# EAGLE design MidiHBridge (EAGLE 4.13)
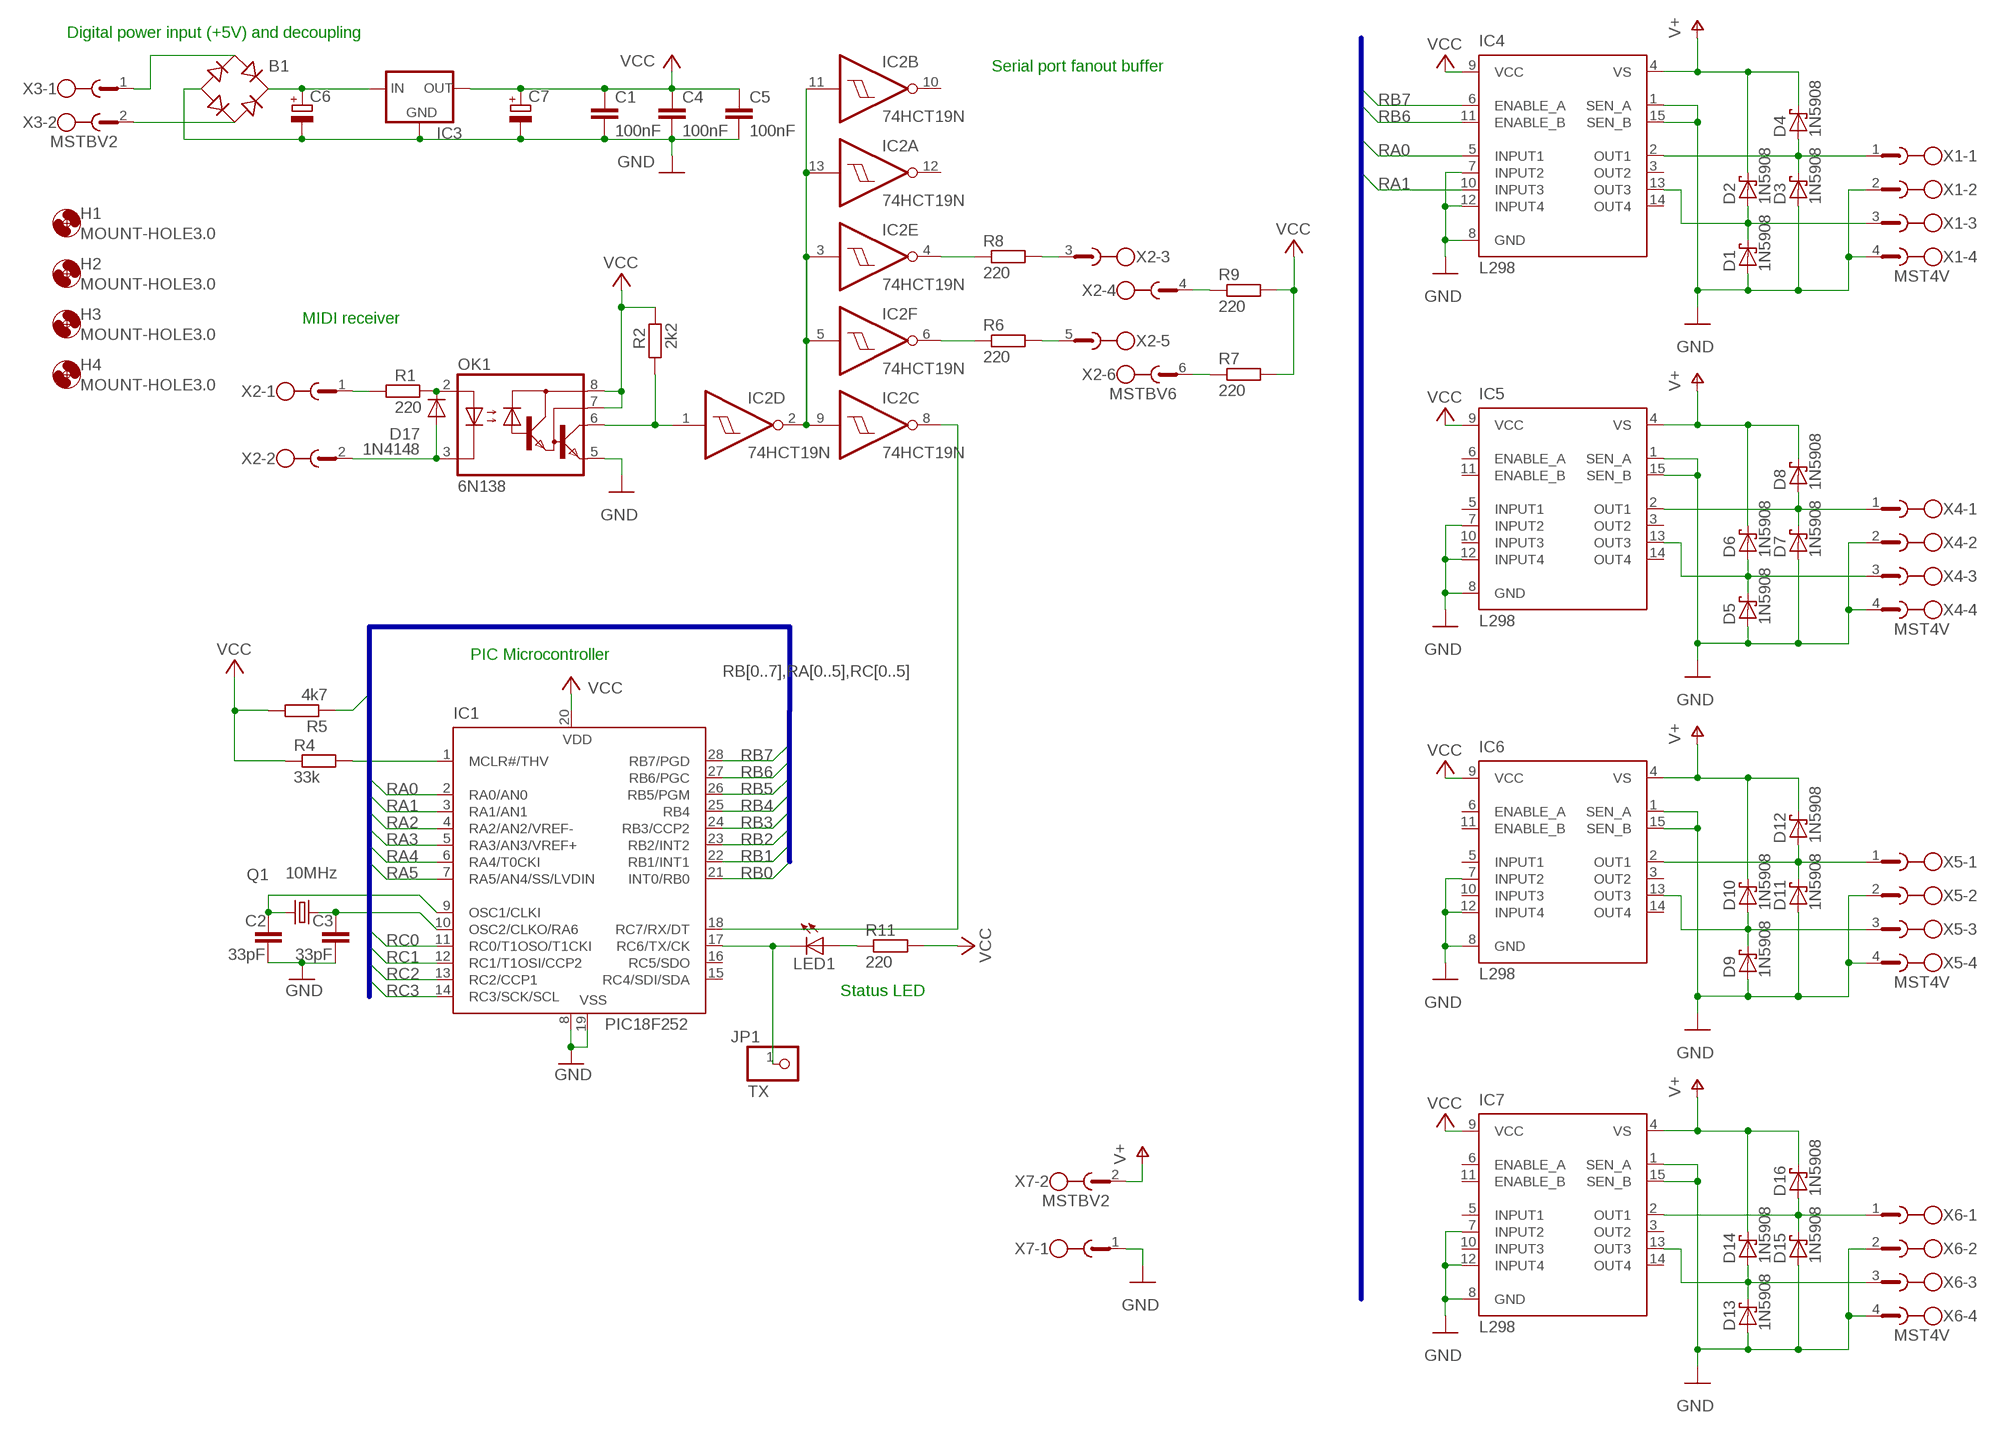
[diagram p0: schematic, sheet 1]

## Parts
B1  RB1A  [RB1A]
C1  100nF  C-EU025-025X050  [C025-025X050]
C2  33pF  C-EU025-025X050  [C025-025X050]
C3  33pF  C-EU025-025X050  [C025-025X050]
C4  100nF  C-EU025-025X050  [C025-025X050]
C5  100nF  C-EU025-025X050  [C025-025X050]
C6  CPOL-EUE5-10.5  [E5-10,5]
C7  CPOL-EUE5-10.5  [E5-10,5]
D1  1N5908  [C4111-15]
D2  1N5908  [C4111-15]
D3  1N5908  [C4111-15]
D4  1N5908  [C4111-15]
D5  1N5908  [C4111-15]
D6  1N5908  [C4111-15]
D7  1N5908  [C4111-15]
D8  1N5908  [C4111-15]
D9  1N5908  [C4111-15]
D10  1N5908  [C4111-15]
D11  1N5908  [C4111-15]
D12  1N5908  [C4111-15]
D13  1N5908  [C4111-15]
D14  1N5908  [C4111-15]
D15  1N5908  [C4111-15]
D16  1N5908  [C4111-15]
D17  1N4148  [DO35-10]
H1  MOUNT-HOLE3.0  [3,0]
H2  MOUNT-HOLE3.0  [3,0]
H3  MOUNT-HOLE3.0  [3,0]
H4  MOUNT-HOLE3.0  [3,0]
IC1  PIC18F252  [DIL28-3]
IC2  74HCT19N  [DIL14]
IC3  78XXS  [78XXS]
IC4  L298  [MULTIWATT-15]
IC5  L298  [MULTIWATT-15]
IC6  L298  [MULTIWATT-15]
IC7  L298  [MULTIWATT-15]
JP1  TX  PINHD-1X1  [1X01]
LED1  LED3MM  [LED3MM]
OK1  6N138  [DIL08]
Q1  10MHz  HC49U70  [HC49U70]
R1  220  R-EU_0204/7  [0204/7]
R2  2k2  R-EU_0204/7  [0204/7]
R4  33k  R-EU_0204/7  [0204/7]
R5  4k7  R-EU_0204/7  [0204/7]
R6  220  R-EU_0204/7  [0204/7]
R7  220  R-EU_0204/7  [0204/7]
R8  220  R-EU_0204/7  [0204/7]
R9  220  R-EU_0204/7  [0204/7]
R11  220  R-EU_0204/7  [0204/7]
X1  MST4V  [MSTBV4]
X2  MSTBV6  [MSTBV6]
X3  MSTBV2  [MSTBV2]
X4  MST4V  [MSTBV4]
X5  MST4V  [MSTBV4]
X6  MST4V  [MSTBV4]
X7  MSTBV2  [MSTBV2]

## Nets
GND: B1.- C1.2 C2.2 C3.2 C4.2 C5.2 C6.- C7.- D1.A D3.A D5.A D7.A D9.A D11.A D13.A D15.A IC1.8(VSS) IC1.19(VSS) IC3.GND IC4.1(SEN_A) IC4.7(INPUT2) IC4.8(GND) IC4.12(INPUT4) IC4.15(SEN_B) IC5.1(SEN_A) IC5.7(INPUT2) IC5.8(GND) IC5.12(INPUT4) IC5.15(SEN_B) IC6.1(SEN_A) IC6.7(INPUT2) IC6.8(GND) IC6.12(INPUT4) IC6.15(SEN_B) IC7.1(SEN_A) IC7.7(INPUT2) IC7.8(GND) IC7.12(INPUT4) IC7.15(SEN_B) OK1.5(GND) X1.2 X1.4 X4.2 X4.4 X5.2 X5.4 X6.2 X6.4 X7.1
N$1: D17.C OK1.2(A) R1.2
N$2: R1.1 X2.1
N$3: C2.1 IC1.9(OSC1/CLKI) Q1.1
N$4: C3.1 IC1.10(OSC2/CLKO/RA6) Q1.2
N$5: D17.A OK1.3(C) X2.2
N$6: D7.C D8.A IC5.2(OUT1) X4.1
N$7: IC1.1(MCLR#/THV) R4.2
N$8: IC2.2(D:O) IC2.3(E:I) IC2.5(F:I) IC2.9(C:I) IC2.11(B:I) IC2.13(A:I)
N$9: IC2.1(D:I) OK1.6(VO) R2.1
N$10: R6.2 X2.5
N$11: IC1.17(RC6/TX/CK) JP1.1 LED1.K(C)
N$13: R7.1 X2.6
N$14: R8.2 X2.3
N$15: R9.1 X2.4
N$16: D5.C D6.A IC5.13(OUT3) X4.3
N$17: IC2.6(F:O) R6.1
N$18: IC2.4(E:O) R8.1
N$19: D11.C D12.A IC6.2(OUT1) X5.1
N$20: D3.C D4.A IC4.2(OUT1) X1.1
N$21: LED1.A R11.1
N$22: B1.+ C6.+ IC3.IN
N$23: B1.AC2 X3.2
N$24: B1.AC1 X3.1
N$25: D1.C D2.A IC4.13(OUT3) X1.3
N$26: D9.C D10.A IC6.13(OUT3) X5.3
N$27: D15.C D16.A IC7.2(OUT1) X6.1
N$28: D13.C D14.A IC7.13(OUT3) X6.3
N$62: IC1.18(RC7/RX/DT) IC2.8(C:O)
RA0: IC1.2(RA0/AN0) IC4.5(INPUT1)
RA1: IC1.3(RA1/AN1) IC4.10(INPUT3)
RA2: IC1.4(RA2/AN2/VREF-)
RA3: IC1.5(RA3/AN3/VREF+)
RA4: IC1.6(RA4/T0CKI) R5.1
RA5: IC1.7(RA5/AN4/SS/LVDIN)
RB0: IC1.21(INT0/RB0)
RB1: IC1.22(RB1/INT1)
RB2: IC1.23(RB2/INT2)
RB3: IC1.24(RB3/CCP2)
RB4: IC1.25(RB4)
RB5: IC1.26(RB5/PGM)
RB6: IC1.27(RB6/PGC) IC4.11(ENABLE_B)
RB7: IC1.28(RB7/PGD) IC4.6(ENABLE_A)
RC0: IC1.11(RC0/T1OSO/T1CKI)
RC1: IC1.12(RC1/T1OSI/CCP2)
RC2: IC1.13(RC2/CCP1)
RC3: IC1.14(RC3/SCK/SCL)
V+: D2.C D4.C D6.C D8.C D10.C D12.C D14.C D16.C IC4.4(VS) IC5.4(VS) IC6.4(VS) IC7.4(VS) X7.2
VCC: C1.1 C4.1 C5.1 C7.+ IC1.20(VDD) IC3.OUT IC4.9(VCC) IC5.9(VCC) IC6.9(VCC) IC7.9(VCC) OK1.7(VB) OK1.8(VCC) R2.2 R4.1 R5.2 R7.2 R9.2 R11.2
Unconnected: IC1.15(RC4/SDI/SDA) IC1.16(RC5/SDO) IC2.10(B:O) IC2.12(A:O) IC4.3(OUT2) IC4.14(OUT4) IC5.3(OUT2) IC5.5(INPUT1) IC5.6(ENABLE_A) IC5.10(INPUT3) IC5.11(ENABLE_B) IC5.14(OUT4) IC6.3(OUT2) IC6.5(INPUT1) IC6.6(ENABLE_A) IC6.10(INPUT3) IC6.11(ENABLE_B) IC6.14(OUT4) IC7.3(OUT2) IC7.5(INPUT1) IC7.6(ENABLE_A) IC7.10(INPUT3) IC7.11(ENABLE_B) IC7.14(OUT4)

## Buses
RB[0..7],RA[0..5],RC[0..5]
RA[0..5],RC[0..5]

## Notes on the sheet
- Digital power input (+5V) and decoupling
- Serial port fanout buffer
- MIDI receiver
- PIC Microcontroller
- Status LED

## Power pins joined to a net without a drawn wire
GND: IC2.7(P:GND)
VCC: IC2.14(P:VCC)

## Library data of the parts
B1 = rectifier:RB1A: RECTIFIER 1 A
C1-C5 = rcl:C-EU: CAPACITOR, European symbol
C6 C7 = rcl:CPOL-EU: POLARIZED CAPACITOR, European symbol
D1-D16 = diode:1N5908: DIODE
D17 = diode:1N4148: DIODE
H1-H4 = holes:MOUNT-HOLE: MOUNTING HOLE with drill center marker
IC1 = microchip:PIC18F252
IC2 = 74xx-eu:74*19: Hex schmitt trigger INVERTER
IC3 = v-reg:78XXS: VOLTAGE REGULATOR
IC4-IC7 = st-microelectronics:L298: DUAL FULL-BRIDGE DRIVER
JP1 = pinhead:PINHD-1X1: PIN HEADER
LED1 = led:LED: LED
OK1 = optocoupler:6N138: MOTOROLA OPTO COUPLER
Q1 = crystal:HC49U70: CRYSTAL
R1 R2 R4-R9 R11 = rcl:R-EU_: RESISTOR, European symbol
X1 X4-X6 = con-phoenix-508:MST4V: PHOENIX
X2 = con-phoenix-508:MSTBV6: PHOENIX
X3 X7 = con-phoenix-508:MSTBV2: PHOENIX

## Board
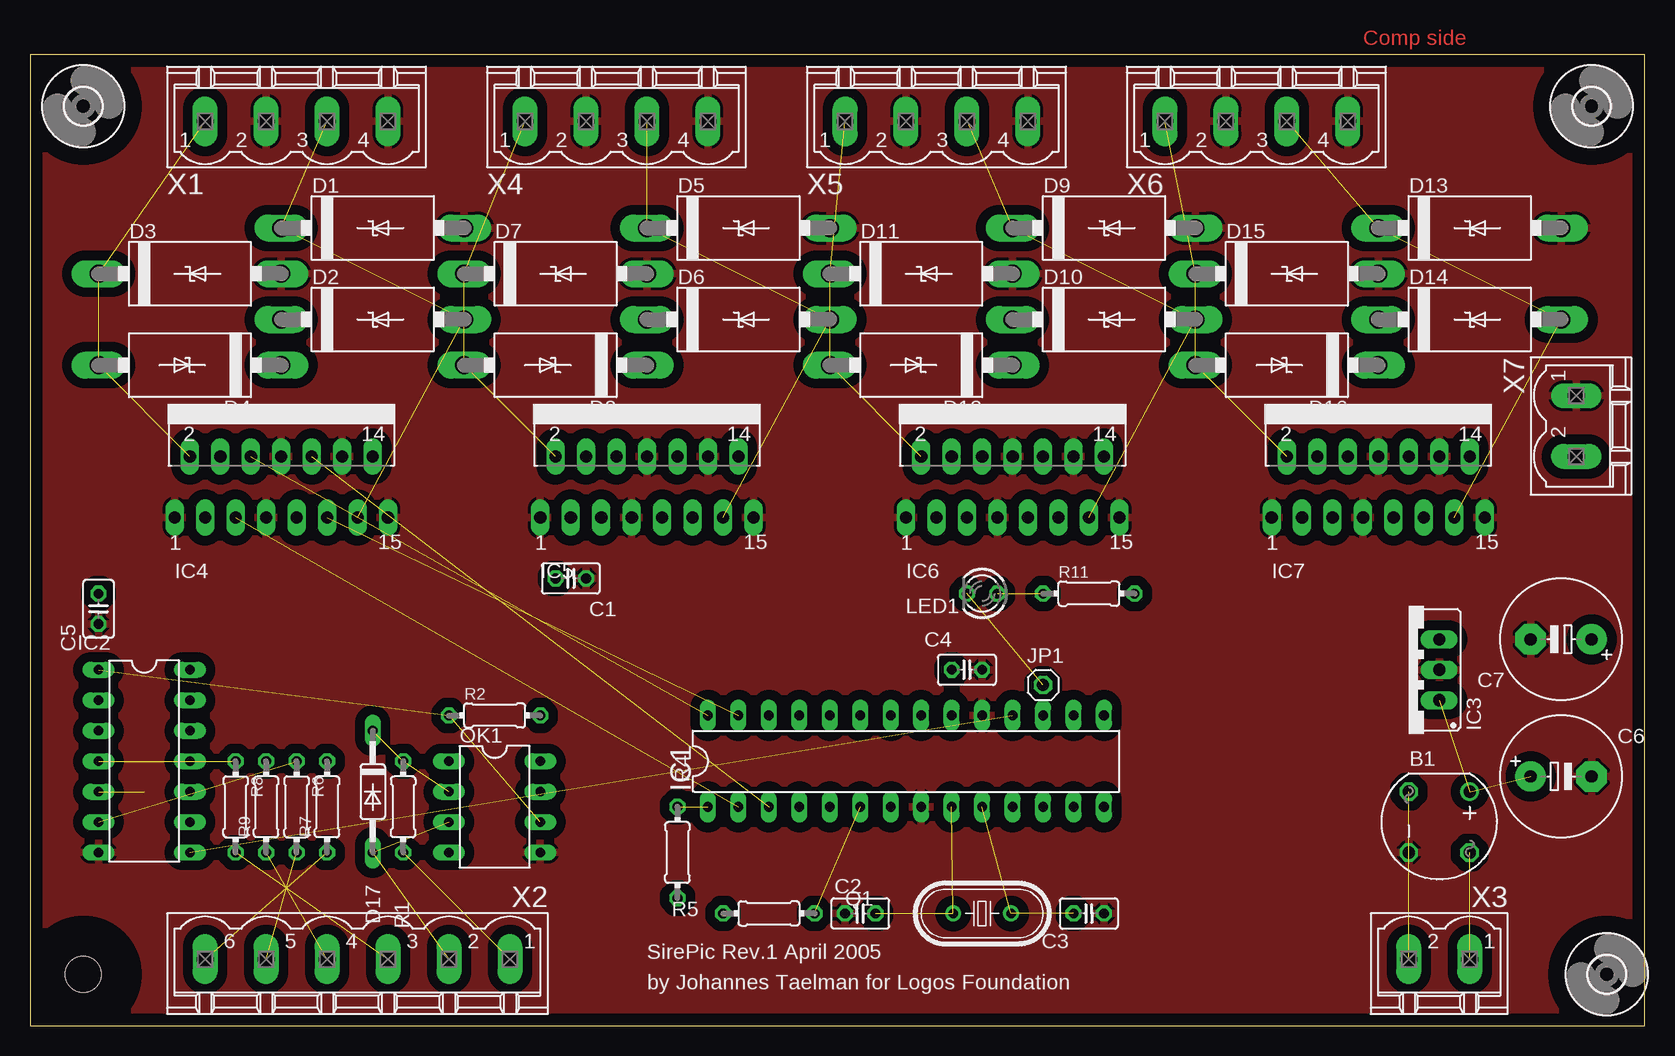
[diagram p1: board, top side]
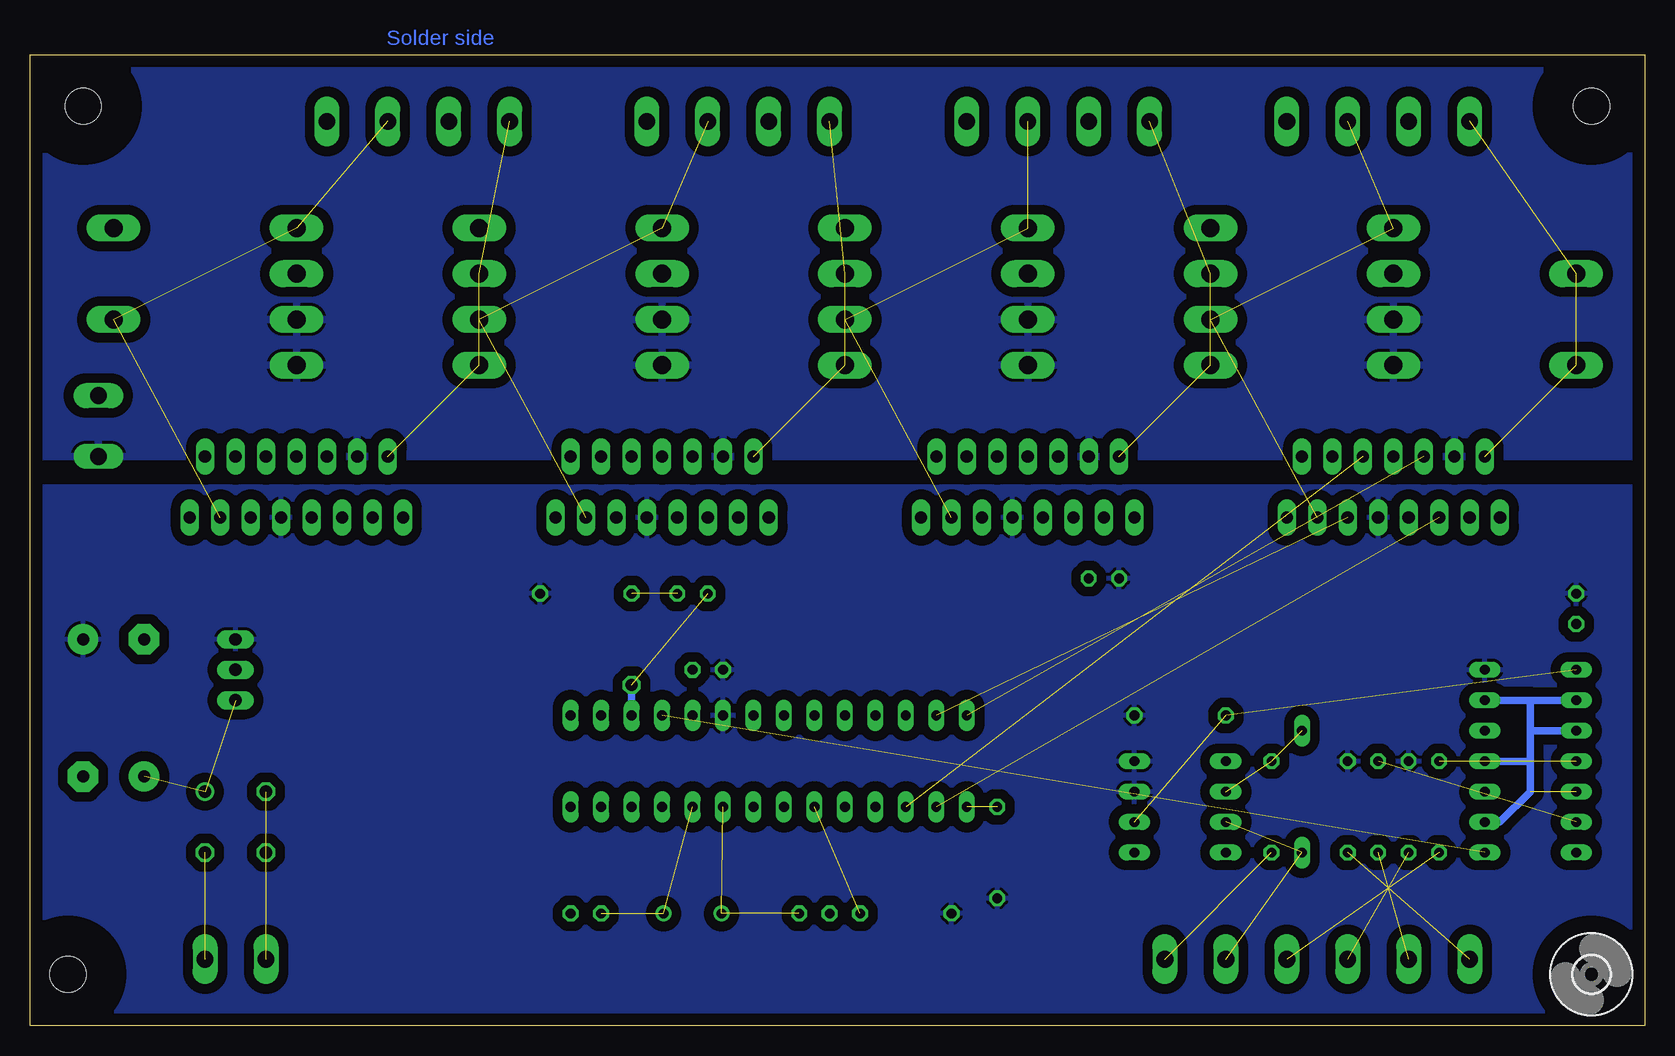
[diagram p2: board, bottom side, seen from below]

Size 134.6 x 80.95 mm. Coordinates in mm from the lower left corner, seen from the top.
Outline: 0,0 134.6,0 134.6,80.95 0,80.95 0,0
Copper layers (1*16): Top 0.035mm / dielectric 1.5mm / Bottom 0.035mm
Design rules "default": minimum track width 10mil, minimum drill 24mil, track to track 8mil, track to pad 8mil, pad to pad 8mil, via to via 8mil, smd to smd 8mil, copper to edge 40mil, drill to drill 8mil, minimum pad ring 10mil, minimum via ring 8mil, stop-mask expansion 0mil, vias tented up to drill 0mil, thermal gap 10mil

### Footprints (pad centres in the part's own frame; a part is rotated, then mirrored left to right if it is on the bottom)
RB1A = drill 1.016 round: + -2.54,2.54 | drill 1.016 octagon: - 2.54,-2.54; AC1 2.54,2.54; AC2 -2.54,-2.54
C025-025X050 = drill 0.813 octagon: 1 -1.27,0; 2 1.27,0
E5-10,5 = drill 1.016 pad 2.54 round: + -2.54,0 | drill 1.016 pad 2.54 octagon: - 2.54,0
C4111-15 = drill 1.499 long: A 7.62,0; C -7.62,0
DO35-10 = drill 0.813 long: A 5.08,0; C -5.08,0
3,0 = hole 3: 0,0
DIL28-3 = drill 0.813 long: 1 -16.51,-3.81; 2 -13.97,-3.81; 3 -11.43,-3.81; 4 -8.89,-3.81; 5 -6.35,-3.81; 6 -3.81,-3.81; 7 -1.27,-3.81; 8 1.27,-3.81; 9 3.81,-3.81; 10 6.35,-3.81; 11 8.89,-3.81; 12 11.43,-3.81; 13 13.97,-3.81; 14 16.51,-3.81; 15 16.51,3.81; 16 13.97,3.81; 17 11.43,3.81; 18 8.89,3.81; 19 6.35,3.81; 20 3.81,3.81; 21 1.27,3.81; 22 -1.27,3.81; 23 -3.81,3.81; 24 -6.35,3.81; 25 -8.89,3.81; 26 -11.43,3.81; 27 -13.97,3.81; 28 -16.51,3.81
DIL14 = drill 0.813 long: 1 -7.62,-3.81; 2 -5.08,-3.81; 3 -2.54,-3.81; 4 0,-3.81; 5 2.54,-3.81; 6 5.08,-3.81; 7 7.62,-3.81; 8 7.62,3.81; 9 5.08,3.81; 10 2.54,3.81; 11 0,3.81; 12 -2.54,3.81; 13 -5.08,3.81; 14 -7.62,3.81
78XXS = drill 1.016 long: GND 0,-2.54; IN -2.54,-2.54; OUT 2.54,-2.54
MULTIWATT-15 = drill 1.016 long: 1 -8.89,-7.62; 2 -7.62,-2.54; 3 -6.35,-7.62; 4 -5.08,-2.54; 5 -3.81,-7.62; 6 -2.54,-2.54; 7 -1.27,-7.62; 8 0,-2.54; 9 1.27,-7.62; 10 2.54,-2.54; 11 3.81,-7.62; 12 5.08,-2.54; 13 6.35,-7.62; 14 7.62,-2.54; 15 8.89,-7.62
1X01 = drill 1.016 octagon: 1 0,0
LED3MM = drill 0.813 octagon: A -1.27,0; K 1.27,0
DIL08 = drill 0.813 long: 1 -3.81,-3.81; 2 -1.27,-3.81; 3 1.27,-3.81; 4 3.81,-3.81; 5 3.81,3.81; 6 1.27,3.81; 7 -1.27,3.81; 8 -3.81,3.81
HC49U70@1 = drill 0.813 round: 1 -2.413,0; 2 2.413,0
0204/7 = drill 0.813 octagon: 1 -3.81,0; 2 3.81,0
MSTBV4 = drill 1.397 long: 1 -7.62,0; 2 -2.54,0; 3 2.54,0; 4 7.62,0
MSTBV6 = drill 1.397 long: 1 -12.7,0; 2 -7.62,0; 3 -2.54,0; 4 2.54,0; 5 7.62,0; 6 12.7,0
MSTBV2 = drill 1.397 long: 1 -2.54,0; 2 2.54,0

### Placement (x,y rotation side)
B1  117.47,16.98 270 top
C1  45.08,37.3 0 top
C2  69.21,9.36 180 top
C3  88.26,9.36 0 top
C4  78.1,29.68 0 top
C5  5.71,34.76 270 top
C6  127.63,20.79 0 top
C7  127.63,32.22 180 top
D1  28.57,66.51 0 top
D2  28.57,58.89 0 top
D3  13.33,62.7 0 top
D4  13.33,55.08 180 top
D5  59.05,66.51 0 top
D6  59.05,58.89 0 top
D7  43.81,62.7 0 top
D8  43.81,55.08 180 top
D9  89.53,66.51 0 top
D10  89.53,58.89 0 top
D11  74.29,62.7 0 top
D12  74.29,55.08 180 top
D13  120.01,66.51 0 top
D14  120.01,58.89 0 top
D15  104.77,62.7 0 top
D16  104.77,55.08 180 top
D17  28.57,19.52 270 top
H1  4.44,4.28 0 bottom
H2  131.44,4.28 0 top
H3  130.17,76.67 0 top
H4  4.44,76.67 0 top
IC1  73.02,22.06 0 top
IC2  9.52,22.06 270 top
IC3  114.93,29.68 90 top
IC4  20.95,50 0 top
IC5  51.43,50 0 top
IC6  81.91,50 0 top
IC7  112.39,50 0 top
JP1  84.45,28.41 0 top
LED1  79.37,36.03 180 top
OK1  38.73,18.25 270 top
Q1  10MHz  [HC49U70@1]  79.37,9.36 0 top
R1  31.11,18.25 90 top
R2  38.73,25.87 0 top
R4  53.97,14.44 90 top
R5  61.59,9.36 180 top
R6  22.22,18.25 270 top
R7  24.76,18.25 90 top
R8  17.14,18.25 270 top
R9  19.68,18.25 90 top
R11  88.26,36.03 0 top
X1  22.22,75.4 0 top
X2  27.3,5.55 180 top
X3  117.47,5.55 180 top
X4  48.89,75.4 0 top
X5  75.56,75.4 0 top
X6  102.23,75.4 0 top
X7  128.9,50 270 top

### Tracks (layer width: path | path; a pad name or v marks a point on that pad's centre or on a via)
GND
  pour Top (isolate 0.813): 0.63,80.48 133.98,80.48 133.98,0.47 0.63,0.47
N$1  (2 unrouted)
N$2  (1 unrouted)
N$3  (2 unrouted)
N$4  (2 unrouted)
N$5  (2 unrouted)
N$6  (3 unrouted)
N$7  (1 unrouted)
N$8  (1 unrouted)
  Bottom 0.61: 9.52,24.6 IC2.3 | 9.52,27.14 IC2.2 | 9.52,24.6 9.52,27.14 | 9.52,22.06 9.52,24.6 | 9.52,22.06 IC2.11 | 9.52,22.06 9.52,19.52 12.06,16.98 IC2.9 | 9.52,27.14 IC2.13
N$9  (2 unrouted)
N$10  (1 unrouted)
N$11  (1 unrouted)
  Bottom 0.61: IC1.17 JP1.1
N$13  (1 unrouted)
N$14  (1 unrouted)
N$15  (1 unrouted)
N$16  (3 unrouted)
N$17  (1 unrouted)
N$18  (1 unrouted)
N$19  (3 unrouted)
N$20  (3 unrouted)
N$21  (1 unrouted)
N$22  (2 unrouted)
N$23  (1 unrouted)
N$24  (1 unrouted)
N$25  (3 unrouted)
N$26  (3 unrouted)
N$27  (3 unrouted)
N$28  (3 unrouted)
N$62  (1 unrouted)
RA0  (1 unrouted)
RA1  (1 unrouted)
RA4  (1 unrouted)
RB6  (1 unrouted)
RB7  (1 unrouted)
V+
  pour Bottom (isolate 0.813): 0.63,80.48 135.25,80.48 135.25,47.46 0.63,47.46
VCC
  pour Bottom (isolate 0.813): 0.63,44.92 133.98,44.92 133.98,0.47 0.63,0.47

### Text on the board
Top: Comp side
Bottom: Solder side
tNames: SirePic Rev.1 April 2005 | by Johannes Taelman for Logos Foundation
